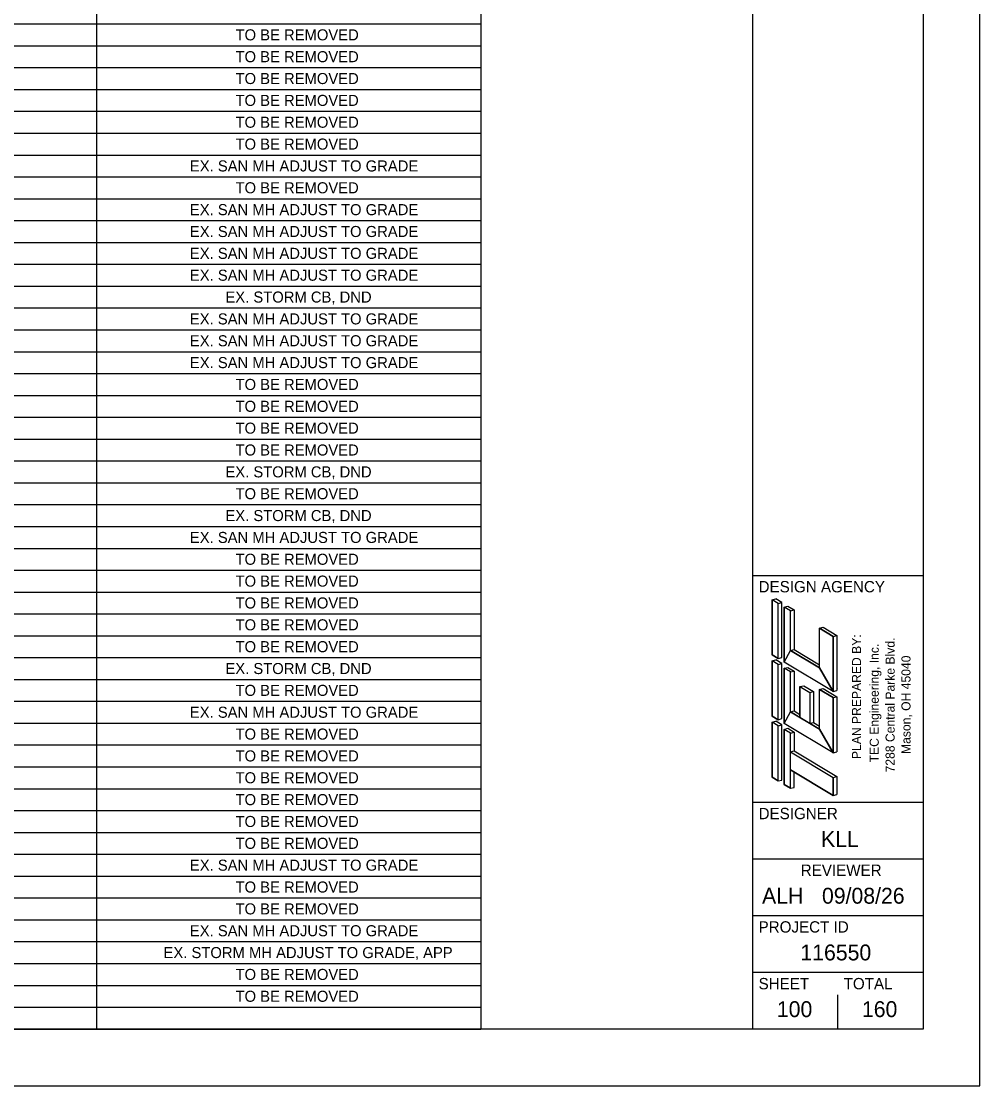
# Model space of a CAD drawing. Extents: x 0 to 34, y 0 to 22.
# Drawn here: x 25.55 to 34, y 0 to 9.39 of the extents above; entities that cross this region are included whole.
import ezdxf

# ---------------------------------------------------------------- set-up
doc = ezdxf.new("R2010")
doc.units = 0
for name, color, linetype in [('Default', 7, 'Continuous'), ('SH_Border', 7, 'Continuous'), ('SH_Cut_Line', 7, 'Continuous'), ('SH_Data', 7, 'Continuous'), ('SH_Text', 7, 'Continuous')]:
    doc.layers.add(name, color=color, linetype=linetype)

msp = doc.modelspace()

# ---------------------------------------------------------------- linework, layer by layer
at = {"layer": 'SH_Border'}
for p, q in [((32, 0.5), (32, 21.5)), ((32, 4.5), (33.5, 4.5)), ((32, 2.5), (33.5, 2.5)), ((32, 2), (33.5, 2)), ((32, 1.5), (33.5, 1.5)), ((32, 1), (33.5, 1))]:
    msp.add_line(p, q, dxfattribs=at)
msp.add_lwpolyline([(1.5, 21.5), (33.5, 21.5), (33.5, 0.5), (1.5, 0.5)], close=True, dxfattribs=at)
at = {"layer": 'SH_Cut_Line'}
msp.add_lwpolyline([(0, 0), (34, 0), (34, 22), (0, 22)], close=True, dxfattribs=at)
at = {"layer": 'SH_Data'}
for p, q in [((32.75, 3.5), (32.75, 3.5)), ((32.75, 0.5), (32.75, 0.8)), ((32.375, 0.675), (32.375, 0.675))]:
    msp.add_line(p, q, dxfattribs=at)
at = {"layer": 'SH_Text'}
for p, q in [((29.6013, 21.5), (29.6013, 0.4995)), ((26.2104, 21.3073), (26.2104, 0.4995)), ((12.8973, 9.3621), (29.6013, 9.3621)), ((12.8973, 9.1694), (29.6013, 9.1694)), ((12.8973, 8.9768), (29.6013, 8.9768)), ((12.8973, 8.7841), (29.6013, 8.7841)), ((12.8973, 8.5914), (29.6013, 8.5914)), ((12.8973, 8.3988), (29.6013, 8.3988)), ((12.8973, 8.2061), (29.6013, 8.2061)), ((12.8973, 8.0134), (29.6013, 8.0134)), ((12.8973, 7.8208), (29.6013, 7.8208)), ((12.8973, 7.6281), (29.6013, 7.6281)), ((12.8973, 7.4355), (29.6013, 7.4355)), ((12.8973, 7.2428), (29.6013, 7.2428)), ((12.8973, 7.0501), (29.6013, 7.0501)), ((12.8973, 6.8575), (29.6013, 6.8575)), ((12.8973, 6.6648), (29.6013, 6.6648)), ((12.8973, 6.4721), (29.6013, 6.4721)), ((12.8973, 6.2795), (29.6013, 6.2795)), ((12.8973, 6.0868), (29.6013, 6.0868)), ((12.8973, 5.8941), (29.6013, 5.8941)), ((12.8973, 5.7015), (29.6013, 5.7015)), ((12.8973, 5.5088), (29.6013, 5.5088)), ((12.8973, 5.3161), (29.6013, 5.3161)), ((12.8973, 5.1235), (29.6013, 5.1235)), ((12.8973, 4.9308), (29.6013, 4.9308)), ((12.8973, 4.7381), (29.6013, 4.7381)), ((12.8973, 4.5455), (29.6013, 4.5455)), ((12.8973, 4.3528), (29.6013, 4.3528)), ((32.1688, 4.2855), (32.2012, 4.2936)), ((32.1688, 3.7995), (32.1688, 4.2855)), ((32.2228, 4.2531), (32.1688, 4.2855)), ((32.2552, 4.2612), (32.2012, 4.2936)), ((32.2228, 4.2531), (32.2552, 4.2612)), ((32.2228, 3.7671), (32.2228, 4.2531)), ((32.2552, 3.7752), (32.2552, 4.2612)), ((32.2768, 4.2207), (32.3092, 4.2288)), ((32.3092, 4.2288), (32.3632, 4.1964)), ((12.8973, 4.1601), (29.6013, 4.1601)), ((32.3308, 4.1883), (32.2768, 4.2207)), ((32.2768, 3.7347), (32.2768, 4.2207)), ((32.3308, 4.1883), (32.3632, 4.1964)), ((32.3308, 3.8373), (32.3308, 4.1883)), ((32.3632, 4.1964), (32.3632, 3.8454)), ((32.5873, 4.0344), (32.6197, 4.0425)), ((32.6197, 4.0425), (32.7412, 3.9696)), ((12.8973, 3.9675), (29.6013, 3.9675)), ((32.5873, 3.6834), (32.5873, 4.0344)), ((32.7088, 3.9615), (32.5873, 4.0344)), ((32.7088, 3.9615), (32.7412, 3.9696)), ((32.7088, 3.4755), (32.7088, 3.9615)), ((32.7412, 3.9696), (32.7412, 3.4836)), ((12.8973, 3.7748), (29.6013, 3.7748)), ((32.2228, 3.7671), (32.1688, 3.7995)), ((32.2228, 3.7671), (32.2552, 3.7752)), ((32.3308, 3.8373), (32.3632, 3.8454)), ((32.5873, 3.6834), (32.3308, 3.8373)), ((32.3632, 3.8454), (32.5873, 3.7109)), ((32.1688, 3.7455), (32.2012, 3.7536)), ((32.1688, 3.2595), (32.1688, 3.7455)), ((32.2228, 3.7131), (32.1688, 3.7455)), ((32.2547, 3.7224), (32.2012, 3.7536)), ((32.2228, 3.7131), (32.2547, 3.7224)), ((32.2228, 3.2271), (32.2228, 3.7131)), ((32.2547, 3.2364), (32.2547, 3.7224)), ((32.7088, 3.4755), (32.2768, 3.7347)), ((32.2768, 3.6807), (32.3092, 3.6888)), ((32.2768, 3.1947), (32.2768, 3.6807)), ((32.3308, 3.6483), (32.2768, 3.6807)), ((32.3092, 3.6888), (32.3632, 3.6564)), ((12.8973, 3.5822), (29.6013, 3.5822)), ((32.3308, 3.6483), (32.3632, 3.6564)), ((32.3308, 3.2973), (32.3308, 3.6483)), ((32.3632, 3.6564), (32.3632, 3.3054)), ((32.4151, 3.5189), (32.4475, 3.527)), ((32.4151, 3.5189), (32.4151, 3.2466)), ((32.4151, 3.5189), (32.5029, 3.4663)), ((32.4475, 3.527), (32.5353, 3.4744)), ((32.5029, 3.4663), (32.5353, 3.4744)), ((32.5353, 3.4744), (32.5353, 3.2021)), ((32.5873, 3.4944), (32.6197, 3.5025)), ((32.5873, 3.1434), (32.5873, 3.4944)), ((32.7088, 3.4215), (32.5873, 3.4944)), ((32.6197, 3.5025), (32.7412, 3.4296)), ((32.7088, 3.4755), (32.7412, 3.4836)), ((12.8973, 3.3895), (29.6013, 3.3895)), ((32.5029, 3.4663), (32.5029, 3.194)), ((32.7088, 3.4215), (32.7412, 3.4296)), ((32.7088, 2.9355), (32.7088, 3.4215)), ((32.7412, 3.4296), (32.7412, 2.9436)), ((32.3308, 3.2973), (32.3632, 3.3054)), ((32.4151, 3.2466), (32.3308, 3.2973)), ((32.3632, 3.3054), (32.4151, 3.2742)), ((12.8973, 3.1968), (29.6013, 3.1968)), ((32.2228, 3.2271), (32.1688, 3.2595)), ((32.1688, 3.2055), (32.2007, 3.2148)), ((32.1688, 2.7195), (32.1688, 3.2055)), ((32.2228, 3.1731), (32.1688, 3.2055)), ((32.2552, 3.1812), (32.2007, 3.2148)), ((32.2228, 3.2271), (32.2547, 3.2364)), ((32.7088, 2.9355), (32.2768, 3.1947)), ((32.5029, 3.194), (32.5353, 3.2021)), ((32.5873, 3.1434), (32.5029, 3.194)), ((32.5353, 3.2021), (32.5873, 3.1709)), ((32.2223, 3.1733), (32.2552, 3.1812)), ((32.2228, 2.6871), (32.2228, 3.1731)), ((32.2552, 2.6952), (32.2552, 3.1812)), ((32.2768, 3.1407), (32.3087, 3.1514)), ((32.3308, 3.1083), (32.2768, 3.1407)), ((32.2768, 2.6547), (32.2768, 3.1407)), ((32.3087, 3.1514), (32.3632, 3.1164)), ((32.3308, 3.1083), (32.3632, 3.1164)), ((32.3308, 2.944), (32.3308, 3.1083)), ((32.3632, 3.1164), (32.3632, 2.9521)), ((12.8973, 3.0042), (29.6013, 3.0042)), ((32.3308, 2.944), (32.3632, 2.9521)), ((32.3308, 2.944), (32.7088, 2.7172)), ((32.3632, 2.9521), (32.7412, 2.7253)), ((32.7088, 2.9355), (32.7412, 2.9436)), ((12.8973, 2.8115), (29.6013, 2.8115)), ((32.3308, 2.7865), (32.7088, 2.5597)), ((32.3308, 2.6223), (32.3308, 2.7865)), ((32.3632, 2.6304), (32.3632, 2.7671)), ((32.7088, 2.7172), (32.7412, 2.7253)), ((32.7412, 2.7253), (32.7412, 2.5678)), ((32.2228, 2.6871), (32.1688, 2.7195)), ((32.2228, 2.6871), (32.2552, 2.6952)), ((32.3308, 2.6223), (32.2768, 2.6547)), ((32.3308, 2.6223), (32.3632, 2.6304)), ((32.7088, 2.5597), (32.7088, 2.7172)), ((12.8973, 2.6188), (29.6013, 2.6188)), ((32.7088, 2.5597), (32.7412, 2.5678)), ((12.8973, 2.4262), (29.6013, 2.4262)), ((12.8973, 2.2335), (29.6013, 2.2335)), ((12.8973, 2.0408), (29.6013, 2.0408)), ((12.8973, 1.8482), (29.6013, 1.8482)), ((12.8973, 1.6555), (29.6013, 1.6555)), ((12.8973, 1.4628), (29.6013, 1.4628)), ((12.8973, 1.2702), (29.6013, 1.2702)), ((12.8973, 1.0775), (29.6013, 1.0775)), ((12.8973, 0.8848), (29.6013, 0.8848)), ((12.8973, 0.6922), (29.6013, 0.6922)), ((12.8973, 0.4995), (29.6013, 0.4995))]:
    msp.add_line(p, q, dxfattribs=at)
for points in [[(32.1688, 3.7995), (32.2228, 3.7671), (32.2228, 4.2531), (32.1688, 4.2855)], [(32.2768, 3.7347), (32.3308, 3.8373), (32.3308, 4.1883), (32.2768, 4.2207)], [(32.7088, 3.4755), (32.5873, 3.6834), (32.5873, 4.0344), (32.7088, 3.9615)], [(32.2768, 3.7347), (32.3308, 3.8373), (32.5873, 3.6834), (32.7088, 3.4755)], [(32.1688, 3.2595), (32.2228, 3.2271), (32.2228, 3.7131), (32.1688, 3.7455)], [(32.2768, 3.1947), (32.3308, 3.2973), (32.3308, 3.6483), (32.2768, 3.6807)], [(32.4151, 3.2466), (32.4151, 3.5189), (32.5029, 3.4663), (32.5029, 3.194)], [(32.7088, 2.9355), (32.5873, 3.1434), (32.5873, 3.4944), (32.7088, 3.4215)], [(32.2768, 3.1947), (32.3308, 3.2973), (32.5873, 3.1434), (32.7088, 2.9355)], [(32.1688, 2.7195), (32.2228, 2.6871), (32.2228, 3.1731), (32.1688, 3.2055)], [(32.2768, 2.6547), (32.3308, 2.6223), (32.3308, 3.1083), (32.2768, 3.1407)], [(32.3308, 2.7865), (32.3308, 2.944), (32.7088, 2.7172), (32.7088, 2.5597)]]:
    msp.add_lwpolyline(points, close=True, dxfattribs=at)

# ---------------------------------------------------------------- texts
at = {"layer": 'Default'}
for s, p in [('PLAN PREPARED BY:', (32.9537, 2.8801)), ('TEC Engineering, Inc.', (33.1097, 2.8507)), ('7288 Central Parke Blvd.', (33.2497, 2.7622)), ('Mason, OH 45040', (33.3897, 2.9246))]:
    msp.add_text(s, height=0.08, rotation=90, dxfattribs=at).set_placement(p)
at = {"layer": 'SH_Data'}
for s, height, p in [('DESIGN AGENCY', 0.1, (32.05, 4.35)), ('DESIGNER', 0.1, (32.05, 2.35)), ('KLL', 0.14, (32.6009, 2.105)), ('REVIEWER', 0.1, (32.4218, 1.85)), ('ALH', 0.14, (32.0804, 1.605)), ('09/08/26', 0.14, (32.6089, 1.605)), ('PROJECT ID', 0.1, (32.05, 1.35)), ('116550', 0.14, (32.4186, 1.105)), ('SHEET', 0.1, (32.05, 0.85)), ('TOTAL', 0.1, (32.8, 0.85)), ('100', 0.14, (32.2112, 0.605)), ('160', 0.14, (32.9612, 0.605))]:
    msp.add_text(s, height=height, dxfattribs=at).set_placement(p)
at = {"layer": 'SH_Text'}
for s, p in [('TO BE REMOVED', (27.4373, 9.217)), ('TO BE REMOVED', (27.4373, 9.0244)), ('TO BE REMOVED', (27.4373, 8.8317)), ('TO BE REMOVED', (27.4373, 8.639)), ('TO BE REMOVED', (27.4373, 8.4464)), ('TO BE REMOVED', (27.4373, 8.2537)), ('EX. SAN MH ADJUST TO GRADE', (27.0347, 8.061)), ('TO BE REMOVED', (27.4373, 7.8684)), ('EX. SAN MH ADJUST TO GRADE', (27.0347, 7.6757)), ('EX. SAN MH ADJUST TO GRADE', (27.0347, 7.483)), ('EX. SAN MH ADJUST TO GRADE', (27.0347, 7.2904)), ('EX. SAN MH ADJUST TO GRADE', (27.0347, 7.0977)), ('EX. STORM CB, DND', (27.3481, 6.905)), ('EX. SAN MH ADJUST TO GRADE', (27.0347, 6.7124)), ('EX. SAN MH ADJUST TO GRADE', (27.0347, 6.5197)), ('EX. SAN MH ADJUST TO GRADE', (27.0347, 6.327)), ('TO BE REMOVED', (27.4373, 6.1344)), ('TO BE REMOVED', (27.4373, 5.9417)), ('TO BE REMOVED', (27.4373, 5.7491)), ('TO BE REMOVED', (27.4373, 5.5564)), ('EX. STORM CB, DND', (27.3481, 5.3637)), ('TO BE REMOVED', (27.4373, 5.1711)), ('EX. STORM CB, DND', (27.3481, 4.9784)), ('EX. SAN MH ADJUST TO GRADE', (27.0347, 4.7857)), ('TO BE REMOVED', (27.4373, 4.5931)), ('TO BE REMOVED', (27.4373, 4.4004)), ('TO BE REMOVED', (27.4373, 4.2077)), ('TO BE REMOVED', (27.4373, 4.0151)), ('TO BE REMOVED', (27.4373, 3.8224)), ('EX. STORM CB, DND', (27.3481, 3.6297)), ('TO BE REMOVED', (27.4373, 3.4371)), ('EX. SAN MH ADJUST TO GRADE', (27.0347, 3.2444)), ('TO BE REMOVED', (27.4373, 3.0517)), ('TO BE REMOVED', (27.4373, 2.8591)), ('TO BE REMOVED', (27.4373, 2.6664)), ('TO BE REMOVED', (27.4373, 2.4737)), ('TO BE REMOVED', (27.4373, 2.2811)), ('TO BE REMOVED', (27.4373, 2.0884)), ('EX. SAN MH ADJUST TO GRADE', (27.0347, 1.8958)), ('TO BE REMOVED', (27.4373, 1.7031)), ('TO BE REMOVED', (27.4373, 1.5104)), ('EX. SAN MH ADJUST TO GRADE', (27.0347, 1.3178)), ('EX. STORM MH ADJUST TO GRADE, APP', (26.8024, 1.1251)), ('TO BE REMOVED', (27.4373, 0.9324)), ('TO BE REMOVED', (27.4373, 0.7398))]:
    msp.add_text(s, height=0.097489, dxfattribs=at).set_placement(p)

doc.saveas('drawing.dxf')
